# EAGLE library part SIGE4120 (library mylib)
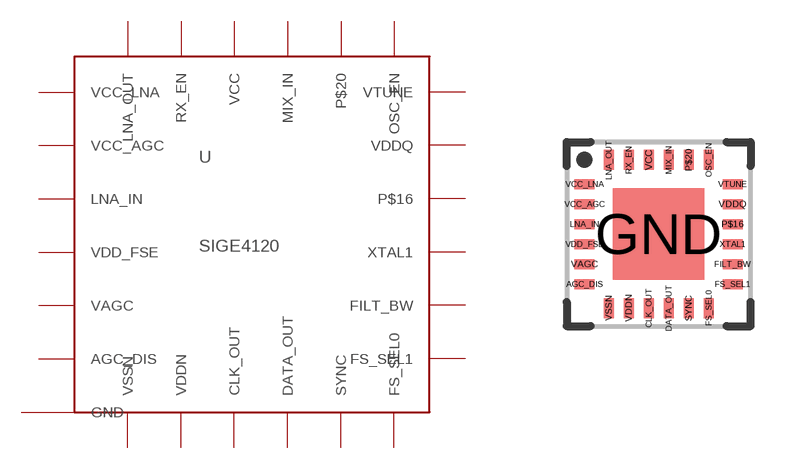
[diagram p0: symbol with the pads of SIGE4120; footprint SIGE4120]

Designator prefix -

## SIGE4120  [SIGE4120]
AGC_DIS  AGC_DIS  in
CLK_OUT  CLK_OUT  out
DATA_OUT  DATA_OUT  out
FILT_BW  FILT_BW  in
FS_SEL0  FS_SEL0  in
FS_SEL1  FS_SEL1  in
GND  GND  in
LNA_IN  LNA_IN  in
LNA_OUT  LNA_OUT  out
MIX_IN  MIX_IN  in
OSC_EN  OSC_EN  in
P$16  P$16  nc
P$20  P$20  nc
RX_EN  RX_EN  in
SYNC  SYNC  out
VAGC  VAGC  in
VCC  VCC  in
VCC_AGC  VCC_AGC  in
VCC_LNA  VCC_LNA  in
VDD_FSE  VDD_FSE  in
VDDN  VDDN  in
VDDQ  VDDQ  in
VSSN  VSSN  in
VTUNE  VTUNE  in
XTAL1  XTAL1  in

## Footprint SIGE4120 (pad centres in mm)
smd 0.5 x 0.25: AGC_DIS -1.85,-1.25; FILT_BW 1.85,-0.75; FS_SEL1 1.85,-1.25; LNA_IN -1.85,0.25; P$16 1.85,0.25; VAGC -1.85,-0.75; VCC_AGC -1.85,0.75; VCC_LNA -1.85,1.25; VDD_FSE -1.85,-0.25; VDDQ 1.85,0.75; VTUNE 1.85,1.25; XTAL1 1.85,-0.25
smd 0.25 x 0.5: CLK_OUT -0.25,-1.85; DATA_OUT 0.25,-1.85; FS_SEL0 1.25,-1.85; LNA_OUT -1.25,1.85; MIX_IN 0.25,1.85; OSC_EN 1.25,1.85; P$20 0.75,1.85; RX_EN -0.75,1.85; SYNC 0.75,-1.85; VCC -0.25,1.85; VDDN -0.75,-1.85; VSSN -1.25,-1.85
smd 2.3 x 2.3: GND 0,0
